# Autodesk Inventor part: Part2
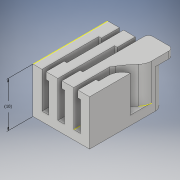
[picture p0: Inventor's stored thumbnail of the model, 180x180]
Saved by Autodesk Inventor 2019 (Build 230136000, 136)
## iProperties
Created: 2019-01
Part Number: Part2
Material: Generic
Document SubType Name: Modeling
Designer: Patel Family
Density: 1 g/cm^3
Appearance: Default
Author: Patel Family
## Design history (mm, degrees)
sketch "Sketch1"
  geometry: L1 (-6.25, 8.25)-(6.25, 8.25); L2 (6.25, 8.25)-(6.25, -8.25); L3 (6.25, -8.25)-(-6.25, -8.25); L4 (-6.25, -8.25)-(-6.25, 8.25); L5 (-6.25, 8.25)-(6.25, -8.25); L6 (6.25, 8.25)-(-6.25, -8.25); 1 further point
  constraints: 12 end point, 2 midpoint, 2 parallel, 1 horizontal, 1 perpendicular
  dimensions: "d0" = 12.5 distance of L2.end L3.end; "d1" = 16.5 distance between parallel lines of L3 L1
extrude "Extrusion1" new body sketch "Sketch1" distance "d2" = 2; taper "d3" = 0 deg
sketch "Sketch2"
  geometry: L1 (6.25, 8.25)-(-6.25, 8.25) reference; L2 (-6.25, 8.25)-(-4.25, 8.25); L3 (-4.25, 8.25)-(-2.75, 8.25); L4 (-2.75, 8.25)-(-0.75, 8.25); L5 (-0.75, 8.25)-(0.75, 8.25); L6 (0.75, 8.25)-(2.75, 8.25); L7 (2.75, 8.25)-(4.25, 8.25); L8 (4.25, 8.25)-(6.25, 8.25); L9 (-6.25, -8.25)-(6.25, -8.25) reference; L10 (-6.25, 8.25)-(-4.25, 8.25); L11 (-4.25, 8.25)-(-4.25, -8.25); L12 (-4.25, -8.25)-(-6.25, -8.25); L13 (-6.25, -8.25)-(-6.25, 8.25); L14 (-2.75, 8.25)-(-0.75, 8.25); L15 (-0.75, 8.25)-(-0.75, -8.25); L16 (-0.75, -8.25)-(-2.75, -8.25); L17 (-2.75, -8.25)-(-2.75, 8.25); L18 (0.75, 8.25)-(2.75, 8.25); L19 (2.75, 8.25)-(2.75, -8.25); L20 (2.75, -8.25)-(0.75, -8.25); L21 (0.75, -8.25)-(0.75, 8.25); L22 (6.25, -8.25)-(6.25, 8.25) reference; L23 (4.25, -8.25)-(6.25, -8.25); L24 (6.25, -8.25)-(6.25, 0.75); L25 (6.25, 0.75)-(4.25, 0.75); L26 (4.25, 0.75)-(4.25, -8.25); 1 further point
  constraints: 46 end point, 11 point on line, 8 parallel, 4 horizontal, 4 perpendicular, 1 collinear
  dimensions: "d4" = 2 distance of L1.end L2.end; "d5" = 1.5 distance of L2.end L3.end; "d6" = 2 distance of L3.end L4.end; "d7" = 1.5 distance of L4.end L5.end; "d8" = 2 distance of L5.end L6.end; "d9" = 1.5 distance of L6.end L7.end; "d10" = 9 distance of L24.end L23.end
extrude "Extrusion2" join sketch "Sketch2" distance "d11" = 8; taper "d12" = 0 deg
sketch "Sketch3"
  geometry: L1 (2.75, -8.25)-(2.75, 8.25) reference; L2 (6.25, 8.25)-(6.25, -8.25) reference; L3 (2.75, 2.436)-(6.25, 2.436); L4 (6.25, 2.436)-(6.25, 8.25); L5 (6.25, 8.25)-(2.75, 8.25); L6 (2.75, 8.25)-(2.75, 2.436); 1 further point
  constraints: 8 end point, 2 parallel, 1 horizontal, 1 perpendicular, 1 point on line
extrude "Extrusion3" join sketch "Sketch3" distance "d13" = 8; taper "d14" = 0 deg
sketch "Sketch4"
  geometry: L1 (5.5, 2)-(5.5, 10) reference; L2 (0, 0)-(0, 10) reference; L3 (5.5, 10)-(0, 10); L4 (0, 10)-(0, 8.5); L5 (0, 8.5)-(5.5, 8.5); L6 (5.5, 8.5)-(5.5, 10); 1 further point
  constraints: 8 end point, 2 parallel, 1 horizontal, 1 perpendicular, 1 point on line
  dimensions: "d15" = 1.5 distance of L4.end L3.end
extrude "Extrusion4" join sketch "Sketch4" distance "d16" = 2; taper "d17" = 0 deg
fillet "Fillet1" dims "d18" = 2
fillet "Fillet2" dims "d19" = 3
fillet "Fillet3" dims "d20" = 3
sketch "Sketch5"
  geometry: L1 (4.573, 2.744)-(2.75, 0); L2 (2.75, -8.25)-(2.75, 2.436) reference; L3 (2.75, 2.744)-(4.573, 2.744); A1 r 3 centre (3.25, 5.436) between (3.25, 2.436) and (6.25, 5.436) reference; 1 further point
  constraints: 4 end point, 1 horizontal, 1 point on circle, 1 point on line
sketch "Sketch6"
  geometry: 1 further point
sketch "Sketch7"
  geometry: L1 (4.675, 2.796)-(2.75, -0.348); L2 (2.75, -8.25)-(2.75, 2.436) reference; L3 (2.75, 2.796)-(4.675, 2.796); L4 (2.75, 2.796)-(2.75, -0.348); A1 r 3 centre (3.25, 5.436) between (3.25, 2.436) and (6.25, 5.436) reference; 1 further point
  constraints: 6 end point, 1 horizontal, 1 perpendicular, 1 point on circle, 1 point on line
extrude "Extrusion5" join sketch "Sketch7" distance "d21" = 8; taper "d22" = 0 deg
fillet "Fillet4" dims "d23" = 19.75
fillet "Fillet5" dims "d24" = 1
sketch "Sketch8"
  geometry: 1 further point
sketch "Sketch9"
  geometry: L1 (0, 10)-(16.5, 10) reference; L2 (16.5, 0)-(0, 0) reference; 1 further point
  dimensions: "d25" = 10 distance between parallel lines of L1 L2 (derived)
sketch "Sketch10"
  geometry: L1 (0, 8)-(16.5, 8) reference; L2 (16.5, 8)-(12.5, 8); L3 (12.5, 8)-(12.5, 6.5); L4 (12.5, 6.5)-(16.5, 6.5); L5 (16.5, 6.5)-(16.5, 8); 1 further point
  constraints: 8 end point, 2 parallel, 1 horizontal, 1 perpendicular
  dimensions: "d26" = 4 distance of L4.end L3.end; "d27" = 1.5 distance of L3.end L2.end
sketch "Sketch11"
  geometry: L1 (16.5, 0)-(16.5, 8) reference; L2 (16.5, 8)-(12.5, 8); L3 (12.5, 8)-(12.5, 6.5); L4 (12.5, 6.5)-(16.5, 6.5); L5 (16.5, 6.5)-(16.5, 8); 1 further point
  constraints: 8 end point, 2 parallel, 1 horizontal, 1 perpendicular
  dimensions: "d28" = 4 distance of L4.end L3.end; "d29" = 1.5 distance of L3.end L2.end
sketch "Sketch12"
  geometry: L1 (0, 8)-(-4, 8); L2 (-4, 8)-(-4, 6.5); L3 (-4, 6.5)-(0, 6.5); L4 (0, 6.5)-(0, 8); 1 further point
  constraints: 8 end point, 2 parallel, 1 horizontal, 1 perpendicular
  dimensions: "d30" = 4 distance of L3.end L2.end; "d31" = 1.5 distance of L2.end L1.end
sketch "Sketch13"
  geometry: L1 (0, 8)-(-4, 8); L2 (-4, 8)-(-4, 6.5); L3 (-4, 6.5)-(0, 6.5); L4 (0, 6.5)-(0, 8); 1 further point
  constraints: 8 end point, 2 parallel, 1 horizontal, 1 perpendicular
  dimensions: "d32" = 4 distance of L3.end L2.end; "d33" = 1.5 distance of L2.end L1.end
sketch "Sketch14"
  geometry: L1 (16.5, 0)-(16.5, 8) reference; L2 (16.5, 8)-(12.5, 8); L3 (12.5, 8)-(12.5, 6.5); L4 (12.5, 6.5)-(16.5, 6.5); L5 (16.5, 6.5)-(16.5, 8); 1 further point
  constraints: 8 end point, 2 parallel, 1 horizontal, 1 perpendicular
  dimensions: "d34" = 4 distance of L4.end L3.end; "d35" = 1.5 distance of L3.end L2.end
extrude "Extrusion6" join sketch "Sketch10" distance "d36" = 0.6; taper "d37" = 0 deg
extrude "Extrusion7" join sketch "Sketch11" distance "d38" = 0.6; taper "d39" = 0 deg
extrude "Extrusion8" join sketch "Sketch12" distance "d40" = 0.6; taper "d41" = 0 deg
extrude "Extrusion9" join sketch "Sketch13" distance "d42" = 0.6; taper "d43" = 0 deg
extrude "Extrusion10" join sketch "Sketch14" distance "d44" = 0.6; taper "d45" = 0 deg
body "Solid1"
